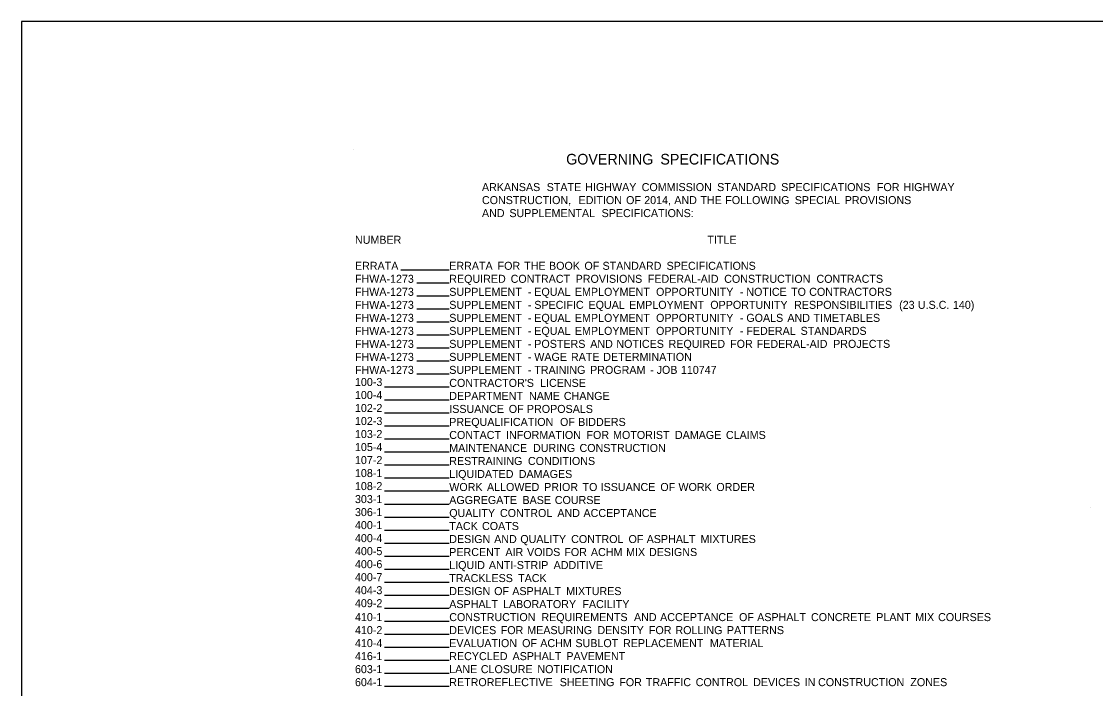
# Model space of a CAD drawing. Extents: x 2262258 to 2263883, y -3124557 to -3123558.
# Drawn here: x 2262258 to 2263063, y -3124058 to -3123558 of the extents above; entities that cross this region are included whole.
import ezdxf

# ---------------------------------------------------------------- set-up
doc = ezdxf.new("R2010")
doc.units = 0
for name, color, linetype in [('Default', 7, 'Continuous'), ('DSN_DRFT_Named-Boundary', 7, 'Continuous'), ('DSN_MISC_Lines', 7, 'Continuous')]:
    doc.layers.add(name, color=color, linetype=linetype)

msp = doc.modelspace()

# ---------------------------------------------------------------- linework, layer by layer
at = {"layer": 'Default'}
for p, q in [((2262507.02, -3123653.97), (2262507.02, -3123653.97)), ((2263059.45, -3123922.37), (2263059.45, -3123922.37))]:
    msp.add_line(p, q, dxfattribs=at)
at = {"layer": 'DSN_DRFT_Named-Boundary'}
msp.add_lwpolyline([(2262257.96, -3124557.39), (2263882.96, -3124557.39), (2263882.96, -3123558.34), (2262257.96, -3123558.34)], close=True, dxfattribs=at)
at = {"layer": 'DSN_MISC_Lines'}
for p, q in [((2262542.45, -3123744.42), (2262578.69, -3123744.42)), ((2262554.39, -3123754.17), (2262578.69, -3123754.17)), ((2262554.39, -3123763.92), (2262578.69, -3123763.92)), ((2262554.39, -3123773.67), (2262578.69, -3123773.67)), ((2262554.39, -3123783.42), (2262578.69, -3123783.42)), ((2262554.39, -3123793.17), (2262578.69, -3123793.17)), ((2262554.39, -3123802.92), (2262578.69, -3123802.92)), ((2262554.39, -3123812.67), (2262578.69, -3123812.67)), ((2262554.39, -3123822.42), (2262578.69, -3123822.42)), ((2262530.14, -3123832.17), (2262578.69, -3123832.17)), ((2262530.14, -3123841.92), (2262578.69, -3123841.92)), ((2262530.14, -3123851.67), (2262578.69, -3123851.67)), ((2262530.14, -3123861.42), (2262578.69, -3123861.42)), ((2262530.14, -3123871.17), (2262578.69, -3123871.17)), ((2262530.14, -3123880.92), (2262578.69, -3123880.92)), ((2262530.14, -3123890.67), (2262578.69, -3123890.67)), ((2262530.14, -3123900.42), (2262578.69, -3123900.42)), ((2262530.14, -3123910.17), (2262578.69, -3123910.17)), ((2262530.14, -3123919.92), (2262578.69, -3123919.92)), ((2262530.14, -3123929.67), (2262578.69, -3123929.67)), ((2262530.14, -3123939.42), (2262578.69, -3123939.42)), ((2262530.14, -3123949.17), (2262578.69, -3123949.17)), ((2262530.14, -3123958.92), (2262578.69, -3123958.92)), ((2262530.14, -3123968.67), (2262578.69, -3123968.67)), ((2262530.14, -3123978.42), (2262578.69, -3123978.42)), ((2262530.14, -3123988.17), (2262578.69, -3123988.17)), ((2262530.14, -3123997.92), (2262578.69, -3123997.92)), ((2262530.14, -3124007.67), (2262578.69, -3124007.67)), ((2262530.14, -3124017.42), (2262578.69, -3124017.42)), ((2262530.14, -3124027.17), (2262578.69, -3124027.17)), ((2262530.14, -3124036.92), (2262578.69, -3124036.92)), ((2262530.14, -3124046.67), (2262578.69, -3124046.67)), ((2262530.14, -3124056.42), (2262578.69, -3124056.42))]:
    msp.add_line(p, q, dxfattribs=at)

# ---------------------------------------------------------------- texts
at = {"layer": 'Default'}
for s, height, p in [('GOVERNING', 8, (2262666.34, -3123665.53)), (' SPECIFICATIONS', 8, (2262733.99, -3123665.53)), ('           ARKANSAS', 6, (2262578.69, -3123685.43)), (' STATE', 6, (2262649.52, -3123685.43)), (' HIGHWAY', 6, (2262678.42, -3123685.43)), (' COMMISSION', 6, (2262720.74, -3123685.43)), (' STANDARD', 6, (2262777.34, -3123685.43)), (' SPECIFICATIONS', 6, (2262825.34, -3123685.43)), (' FOR', 6, (2262897.11, -3123685.43)), (' HIGHWAY', 6, (2262917.02, -3123685.43)), ('           CONSTRUCTION,', 6, (2262578.69, -3123695.18)), (' EDITION', 6, (2262673.41, -3123695.18)), (' OF', 6, (2262709.05, -3123695.18)), (' 2014,', 6, (2262722.64, -3123695.18)), (' AND', 6, (2262745.19, -3123695.18)), (' THE', 6, (2262764.77, -3123695.18)), (' FOLLOWING', 6, (2262783.42, -3123695.18)), (' SPECIAL', 6, (2262835.52, -3123695.18)), (' PROVISIONS', 6, (2262872.97, -3123695.18)), ('           AND', 6, (2262578.69, -3123704.93)), (' SUPPLEMENTAL', 6, (2262621.55, -3123704.93)), (' SPECIFICATIONS:', 6, (2262690.67, -3123704.93)), ('NUMBER', 6, (2262508, -3123724.92)), ('TITLE', 6, (2262772.24, -3123724.92)), ('ERRATA', 6, (2262508, -3123744.42)), ('ERRATA', 6, (2262578.69, -3123744.42)), (' FOR', 6, (2262612.71, -3123744.42)), (' THE', 6, (2262632.62, -3123744.42)), (' BOOK', 6, (2262651.27, -3123744.42)), (' OF', 6, (2262677.81, -3123744.42)), (' STANDARD', 6, (2262691.4, -3123744.42)), (' SPECIFICATIONS', 6, (2262739.4, -3123744.42)), ('FHWA-1273', 6, (2262508, -3123754.17)), ('REQUIRED', 6, (2262578.69, -3123754.17)), (' CONTRACT', 6, (2262622.49, -3123754.17)), (' PROVISIONS', 6, (2262671.23, -3123754.17)), (' FEDERAL-AID', 6, (2262725.3, -3123754.17)), (' CONSTRUCTION', 6, (2262782.61, -3123754.17)), (' CONTRACTS', 6, (2262851.79, -3123754.17)), ('FHWA-1273', 6, (2262508, -3123763.92)), ('SUPPLEMENT', 6, (2262578.69, -3123763.92)), (' -', 6, (2262635.36, -3123763.92)), (' EQUAL', 6, (2262640.21, -3123763.92)), (' EMPLOYMENT', 6, (2262670.67, -3123763.92)), (' OPPORTUNITY', 6, (2262731.52, -3123763.92)), (' -', 6, (2262794.34, -3123763.92)), (' NOTICE', 6, (2262799.2, -3123763.92)), (' TO', 6, (2262832.75, -3123763.92)), (' CONTRACTORS', 6, (2262846.35, -3123763.92)), ('FHWA-1273', 6, (2262508, -3123773.67)), ('SUPPLEMENT', 6, (2262578.69, -3123773.67)), (' -', 6, (2262635.36, -3123773.67)), (' SPECIFIC', 6, (2262640.21, -3123773.67)), (' EQUAL', 6, (2262680.87, -3123773.67)), (' EMPLOYMENT', 6, (2262711.33, -3123773.67)), (' OPPORTUNITY', 6, (2262772.18, -3123773.67)), (' RESPONSIBILITIES', 6, (2262835, -3123773.67)), (' (23', 6, (2262913.77, -3123773.67)), (' U.S.C.', 6, (2262927.82, -3123773.67)), (' 140)', 6, (2262954.11, -3123773.67)), ('FHWA-1273', 6, (2262508, -3123783.42)), ('SUPPLEMENT', 6, (2262578.69, -3123783.42)), (' EQUAL', 6, (2262640.21, -3123783.42)), (' EMPLOYMENT', 6, (2262670.67, -3123783.42)), (' OPPORTUNITY', 6, (2262731.52, -3123783.42)), (' GOALS', 6, (2262799.2, -3123783.42)), (' AND', 6, (2262829.98, -3123783.42)), (' TIMETABLES', 6, (2262849.56, -3123783.42)), ('FHWA-1273', 6, (2262508, -3123793.17)), ('SUPPLEMENT', 6, (2262578.69, -3123793.17)), (' -', 6, (2262635.36, -3123783.42)), (' EQUAL', 6, (2262640.21, -3123793.17)), (' EMPLOYMENT', 6, (2262670.67, -3123793.17)), (' OPPORTUNITY', 6, (2262731.52, -3123793.17)), (' -', 6, (2262794.34, -3123783.42)), (' FEDERAL', 6, (2262799.2, -3123793.17)), (' STANDARDS', 6, (2262839.9, -3123793.17)), (' -', 6, (2262635.36, -3123793.17)), (' -', 6, (2262794.34, -3123793.17)), ('FHWA-1273', 6, (2262508, -3123802.92)), ('SUPPLEMENT', 6, (2262578.69, -3123802.92)), (' -', 6, (2262635.36, -3123802.92)), (' POSTERS', 6, (2262640.21, -3123802.92)), (' AND', 6, (2262682.17, -3123802.92)), (' NOTICES', 6, (2262701.75, -3123802.92)), (' REQUIRED', 6, (2262740.91, -3123802.92)), (' FOR', 6, (2262787.04, -3123802.92)), (' FEDERAL-AID', 6, (2262806.96, -3123802.92)), (' PROJECTS', 6, (2262864.27, -3123802.92)), ('FHWA-1273', 6, (2262508, -3123812.67)), ('SUPPLEMENT', 6, (2262578.69, -3123812.67)), (' -', 6, (2262635.36, -3123812.67)), (' WAGE', 6, (2262640.21, -3123812.67)), (' RATE', 6, (2262667.71, -3123812.67)), (' DETERMINATION', 6, (2262691.95, -3123812.67)), ('FHWA-1273', 6, (2262508, -3123822.42)), ('SUPPLEMENT', 6, (2262578.69, -3123822.42)), (' TRAINING', 6, (2262640.21, -3123822.42)), (' PROGRAM', 6, (2262682.07, -3123822.42)), (' JOB', 6, (2262731.95, -3123822.42)), (' 110747', 6, (2262750.13, -3123822.42)), ('100-3', 6, (2262508, -3123831.49)), ("CONTRACTOR'S", 6, (2262578.69, -3123832.17)), (' -', 6, (2262635.36, -3123822.42)), (' LICENSE', 6, (2262644.59, -3123832.17)), (' -', 6, (2262727.09, -3123822.42)), ('100-4', 6, (2262508, -3123841.24)), ('DEPARTMENT', 6, (2262578.69, -3123841.92)), (' NAME', 6, (2262636.28, -3123841.92)), (' CHANGE', 6, (2262662.38, -3123841.92)), ('102-2', 6, (2262508, -3123850.99)), ('ISSUANCE', 6, (2262578.69, -3123851.67)), (' OF', 6, (2262621.1, -3123851.67)), (' PROPOSALS', 6, (2262634.69, -3123851.67)), ('102-3', 6, (2262508, -3123860.74)), ('PREQUALIFICATION', 6, (2262578.69, -3123861.42)), (' OF', 6, (2262659.52, -3123861.42)), (' BIDDERS', 6, (2262673.11, -3123861.42)), ('103-2', 6, (2262508, -3123870.49)), ('CONTACT', 6, (2262578.69, -3123871.17)), (' INFORMATION', 6, (2262619.04, -3123871.17)), (' FOR', 6, (2262679.36, -3123871.17)), (' MOTORIST', 6, (2262699.28, -3123871.17)), (' DAMAGE', 6, (2262745.68, -3123871.17)), (' CLAIMS', 6, (2262783.9, -3123871.17)), ('105-4', 6, (2262508, -3123880.24)), ('MAINTENANCE', 6, (2262578.69, -3123880.92)), (' DURING', 6, (2262639.26, -3123880.92)), (' CONSTRUCTION', 6, (2262674.13, -3123880.92)), ('107-2', 6, (2262508, -3123889.99)), ('RESTRAINING', 6, (2262578.69, -3123890.67)), (' CONDITIONS', 6, (2262635.46, -3123890.67)), ('108-1', 6, (2262508, -3123899.74)), ('LIQUIDATED', 6, (2262578.69, -3123900.42)), (' DAMAGES', 6, (2262628.55, -3123900.42)), ('108-2', 6, (2262508, -3123909.49)), ('WORK', 6, (2262578.69, -3123910.17)), (' ALLOWED', 6, (2262604.75, -3123910.17)), (' PRIOR', 6, (2262647.62, -3123910.17)), (' TO', 6, (2262676.39, -3123910.17)), (' ISSUANCE', 6, (2262689.98, -3123910.17)), (' OF', 6, (2262734.73, -3123910.17)), (' WORK', 6, (2262748.31, -3123910.17)), (' ORDER', 6, (2262776.7, -3123910.17)), ('303-1', 6, (2262508, -3123919.24)), ('AGGREGATE', 6, (2262578.69, -3123919.92)), (' BASE', 6, (2262631.35, -3123919.92)), (' COURSE', 6, (2262655.6, -3123919.92)), ('306-1', 6, (2262508, -3123928.99)), ('QUALITY', 6, (2262578.69, -3123929.67)), (' CONTROL', 6, (2262614.49, -3123929.67)), (' AND', 6, (2262657.51, -3123929.67)), (' ACCEPTANCE', 6, (2262677.1, -3123929.67)), ('400-1', 6, (2262508, -3123938.74)), ('TACK', 6, (2262578.69, -3123939.42)), (' COATS', 6, (2262601.03, -3123939.42)), ('400-4', 6, (2262508, -3123948.49)), ('DESIGN', 6, (2262578.69, -3123949.17)), (' AND', 6, (2262610.14, -3123949.17)), (' QUALITY', 6, (2262629.73, -3123949.17)), (' CONTROL', 6, (2262667.86, -3123949.17)), (' OF', 6, (2262710.88, -3123949.17)), (' ASPHALT', 6, (2262724.47, -3123949.17)), (' MIXTURES', 6, (2262764.84, -3123949.17)), ('400-5', 6, (2262508, -3123958.24)), ('PERCENT', 6, (2262578.69, -3123958.92)), (' AIR', 6, (2262618.58, -3123958.92)), (' VOIDS', 6, (2262634.77, -3123958.92)), (' FOR', 6, (2262662.75, -3123958.92)), (' ACHM', 6, (2262682.66, -3123958.92)), (' MIX', 6, (2262709.04, -3123958.92)), (' DESIGNS', 6, (2262726.22, -3123958.92)), ('400-6', 6, (2262508, -3123967.99)), ('LIQUID', 6, (2262578.69, -3123968.67)), (' ANTI-STRIP', 6, (2262606.18, -3123968.67)), (' ADDITIVE', 6, (2262654.72, -3123968.67)), ('400-7', 6, (2262508, -3123977.74)), ('TRACKLESS', 6, (2262578.69, -3123978.42)), (' TACK', 6, (2262628.1, -3123978.42)), ('404-3', 6, (2262508, -3123987.49)), ('DESIGN', 6, (2262578.69, -3123988.17)), (' OF', 6, (2262610.14, -3123988.17)), (' ASPHALT', 6, (2262623.73, -3123988.17)), (' MIXTURES', 6, (2262664.1, -3123988.17)), ('409-2', 6, (2262508, -3123997.24)), ('ASPHALT', 6, (2262578.69, -3123997.92)), (' LABORATORY', 6, (2262616.73, -3123997.92)), (' FACILITY', 6, (2262676.3, -3123997.92)), ('410-1', 6, (2262508, -3124007.67)), ('CONSTRUCTION', 6, (2262578.69, -3124007.67)), (' REQUIREMENTS', 6, (2262645.54, -3124007.67)), (' AND', 6, (2262714.97, -3124007.67)), (' ACCEPTANCE', 6, (2262734.55, -3124007.67)), (' OF', 6, (2262793.74, -3124007.67)), (' ASPHALT', 6, (2262807.33, -3124007.67)), (' CONCRETE', 6, (2262847.69, -3124007.67)), (' PLANT', 6, (2262896.62, -3124007.67)), (' MIX', 6, (2262925.8, -3124007.67)), (' COURSES', 6, (2262942.98, -3124007.67)), ('410-2', 6, (2262508, -3124017.42)), ('DEVICES', 6, (2262578.69, -3124017.42)), (' FOR', 6, (2262615.06, -3124017.42)), (' MEASURING', 6, (2262634.97, -3124017.42)), (' DENSITY', 6, (2262687.55, -3124017.42)), (' FOR', 6, (2262726.15, -3124017.42)), (' ROLLING', 6, (2262746.06, -3124017.42)), (' PATTERNS', 6, (2262784.66, -3124017.42)), ('410-4', 6, (2262508, -3124027.17)), ('EVALUATION', 6, (2262578.69, -3124027.17)), (' OF', 6, (2262631.11, -3124027.17)), (' ACHM', 6, (2262644.7, -3124027.17)), (' SUBLOT', 6, (2262671.08, -3124027.17)), (' REPLACEMENT', 6, (2262706.78, -3124027.17)), (' MATERIAL', 6, (2262771.84, -3124027.17)), ('416-1', 6, (2262508, -3124036.92)), ('RECYCLED', 6, (2262578.69, -3124036.92)), (' ASPHALT', 6, (2262623.9, -3124036.92)), (' PAVEMENT', 6, (2262664.26, -3124036.92)), ('603-1', 6, (2262508, -3124046.67)), ('LANE', 6, (2262578.69, -3124046.67)), (' CLOSURE', 6, (2262600.14, -3124046.67)), (' NOTIFICATION', 6, (2262642.55, -3124046.67)), ('604-1', 6, (2262508, -3124056.42)), ('RETROREFLECTIVE', 6, (2262578.69, -3124056.42)), (' SHEETING', 6, (2262659.3, -3124056.42)), (' FOR', 6, (2262703.96, -3124056.42)), (' TRAFFIC', 6, (2262723.87, -3124056.42)), (' CONTROL', 6, (2262761.26, -3124056.42)), (' DEVICES', 6, (2262804.28, -3124056.42)), (' IN', 6, (2262842.98, -3124056.42)), (' CONSTRUCTION', 6, (2262853, -3124056.42)), (' ZONES', 6, (2262922.18, -3124056.42))]:
    msp.add_text(s, height=height, dxfattribs=at).set_placement(p)

doc.saveas('drawing.dxf')
